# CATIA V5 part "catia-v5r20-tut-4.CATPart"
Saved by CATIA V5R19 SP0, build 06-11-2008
Part number: c02tut4
Bounding box of the stored display mesh (mm): x 0 to 0, y -50 to 100, z -30 to 49.981
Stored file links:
  D:\Shriniwas\v5_r19\Part files\c02\c02tut4.CATPart
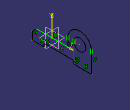
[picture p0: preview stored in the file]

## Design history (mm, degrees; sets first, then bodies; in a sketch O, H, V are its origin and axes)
Body1 (main body)
  Sketch1 on yz-plane, origin (0, 0, 0), H (0, 1, 0), V (0, 0, 1)
    line L1 (-50, -30) -> (-20, -30)
    line L2 (-20, -30) -> (-20, -22)
    line L3 (-20, -22) -> (55, -22)
    line L4 (55, -22) -> (55, -30)
    point P5 (55, -30)
    line L5 (55, -30) -> (100, -30)
    line L6 (100, -30) -> (100, 20)
    arc A1 centre (70, 20) radius 30 from (100, 20) to (40, 20) ccw
    line L7 (40, 20) -> (40, 0)
    point P10 (40, 0)
    line L8 (40, 0) -> (-40, 0)
    line L9 (-40, 0) -> (-50, -10)
    line L10 (-50, -10) -> (-50, -30)
    circle A2 centre (70, 20) radius 15
    length L2 = 8
    length L3 = 75
    horizontal: L1 H, L3 H, L5 H, L8 H
    vertical: L2 V, L4 V, L6 V, L10 V
    coincidence: P5 L1, P10 H
    tangency: A1 L6, L7 A1, A2 L4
